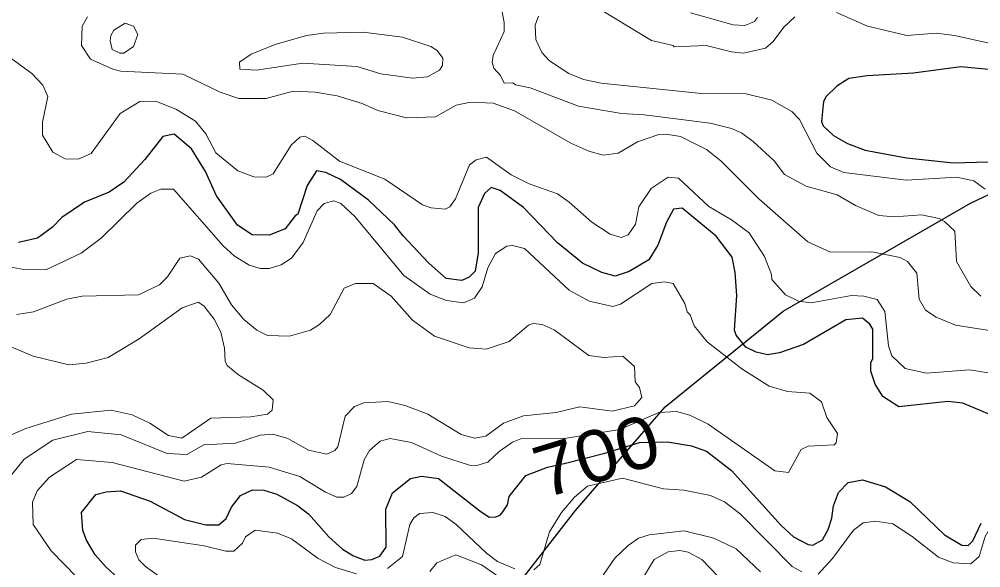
# Model space of a CAD drawing. Extents: x 673.3 to 698.5, y 6984.3 to 7012.3.
# Drawn here: x 674.164 to 675.656, y 6993.355 to 6994.206 of the extents above; entities that cross this region are included whole.
import ezdxf
from ezdxf.enums import TextEntityAlignment as Align

# ---------------------------------------------------------------- set-up
doc = ezdxf.new("R2010")
doc.units = 0
doc.header["$LTSCALE"] = 0.032
for name, color, linetype, lineweight in [('1', 7, 'Continuous', 25), ('2', 7, 'Continuous', 13), ('26', 7, 'Continuous', 25)]:
    doc.layers.add(name, color=color, linetype=linetype, lineweight=lineweight)
doc.layers.add('61', color=7, linetype='Continuous')

msp = doc.modelspace()

# ---------------------------------------------------------------- linework, layer by layer
at = {"layer": '1'}
for points in [[(675.7598, 6994.1193), (675.6253, 6994.1323), (675.552, 6994.1225), (675.4798, 6994.1185), (675.4514, 6994.1143), (675.4328, 6994.1022), (675.4162, 6994.0865), (675.4121, 6994.0786), (675.4092, 6994.0475), (675.4117, 6994.0409), (675.4277, 6994.026), (675.4494, 6994.0136), (675.477, 6994.0033), (675.5412, 6993.9914), (675.6139, 6993.9833), (675.6679, 6993.9849)], [(675.6679, 6993.594), (675.6285, 6993.6103), (675.6053, 6993.6128), (675.5289, 6993.6046), (675.5043, 6993.6208), (675.4923, 6993.6398), (675.4856, 6993.6599), (675.4856, 6993.673), (675.4888, 6993.6796), (675.4889, 6993.7253), (675.484, 6993.733), (675.4725, 6993.7421), (675.447, 6993.7396), (675.381, 6993.7014), (675.3441, 6993.6885), (675.3253, 6993.6854), (675.3077, 6993.6894), (675.2917, 6993.6975), (675.2765, 6993.7159), (675.2739, 6993.7235), (675.2778, 6993.7775), (675.2754, 6993.813), (675.2703, 6993.8369), (675.2457, 6993.8696), (675.1931, 6993.9131), (675.1797, 6993.9115), (675.1688, 6993.8913), (675.1551, 6993.8557), (675.1411, 6993.8328), (675.1106, 6993.8145), (675.089, 6993.8075), (675.0681, 6993.8129), (675.0384, 6993.8278), (674.9996, 6993.8593), (674.9467, 6993.9138), (674.9104, 6993.9405), (674.8968, 6993.9449), (674.8862, 6993.936), (674.8764, 6993.914), (674.8763, 6993.8437), (674.8717, 6993.8152), (674.8624, 6993.8061), (674.8512, 6993.8009), (674.8267, 6993.8039), (674.7998, 6993.8277), (674.7594, 6993.8706), (674.7466, 6993.8874), (674.7064, 6993.9252), (674.6627, 6993.9574), (674.6402, 6993.9686), (674.6256, 6993.9709), (674.611, 6993.9483), (674.5966, 6993.9035), (674.5925, 6993.9013), (674.5771, 6993.8811), (674.5522, 6993.871), (674.526, 6993.8715), (674.5031, 6993.8867), (674.4707, 6993.9322), (674.4536, 6993.9697), (674.4317, 6994.0052), (674.4048, 6994.0279), (674.3872, 6994.0241), (674.3591, 6993.9885), (674.3267, 6993.9534), (674.3041, 6993.9378), (674.2656, 6993.9222), (674.2305, 6993.8985), (674.2161, 6993.8835), (674.1925, 6993.8662), (674.1633, 6993.8596)], [(674.3319, 6993.3258), (674.2984, 6993.3567), (674.2823, 6993.3751), (674.2687, 6993.3978), (674.2631, 6993.4127), (674.2608, 6993.4406), (674.2831, 6993.4687), (674.2995, 6993.4728), (674.3217, 6993.4742), (674.3676, 6993.4583), (674.4206, 6993.4295), (674.4538, 6993.4217), (674.4743, 6993.4216), (674.4854, 6993.4312), (674.4935, 6993.4487), (674.5075, 6993.4668), (674.5262, 6993.4759), (674.5439, 6993.4751), (674.5643, 6993.4692), (674.596, 6993.4516), (674.6136, 6993.4382), (674.6448, 6993.4029), (674.6662, 6993.3839), (674.6828, 6993.3732), (674.7006, 6993.3668), (674.7113, 6993.3676), (674.7241, 6993.3726), (674.7335, 6993.3867), (674.7334, 6993.4459), (674.7437, 6993.471), (674.7713, 6993.4932), (674.7884, 6993.497), (674.8147, 6993.4936), (674.8789, 6993.443), (674.8936, 6993.4336), (674.904, 6993.4337), (674.9106, 6993.4367), (674.9146, 6993.4418), (674.9219, 6993.4524), (674.9243, 6993.4654), (674.9505, 6993.4978), (674.9842, 6993.511), (675.0101, 6993.5165), (675.073, 6993.5326), (675.1268, 6993.5494), (675.17, 6993.5504), (675.2074, 6993.5442), (675.2307, 6993.5358), (675.2696, 6993.5056), (675.3464, 6993.4204), (675.3656, 6993.4028), (675.3886, 6993.391), (675.3959, 6993.3901), (675.4108, 6993.398), (675.4195, 6993.4141)], [(675.4195, 6993.4141), (675.4252, 6993.4319), (675.4277, 6993.4512), (675.4356, 6993.4716), (675.4506, 6993.4872), (675.4728, 6993.4913), (675.5086, 6993.4806), (675.5464, 6993.4575), (675.5998, 6993.4057), (675.6266, 6993.3899), (675.6367, 6993.3896), (675.6439, 6993.3968), (675.6567, 6993.4241)]]:
    msp.add_lwpolyline(points, dxfattribs=at)
at = {"layer": '2'}
for points in [[(674.9114, 6994.2283), (674.917, 6994.201), (674.917, 6994.1871), (674.8996, 6994.1499), (674.8983, 6994.1392), (674.9005, 6994.1304), (674.9112, 6994.1187), (674.9166, 6994.1072), (674.93, 6994.1077), (674.9342, 6994.1044), (674.9572, 6994.0999), (675.0321, 6994.0714), (675.0989, 6994.0599), (675.134, 6994.0581), (675.2366, 6994.0451), (675.2695, 6994.0368), (675.285, 6994.0298)], [(675.3677, 6994.21), (675.3507, 6994.1939), (675.3342, 6994.1717), (675.3223, 6994.1616), (675.288, 6994.1536), (675.2695, 6994.1558), (675.2301, 6994.1656), (675.1804, 6994.1633), (675.179, 6994.1656), (675.1451, 6994.1734), (675.0694, 6994.2193)], [(675.3096, 6994.209), (675.3052, 6994.2029), (675.2902, 6994.1967), (675.2719, 6994.1975), (675.206, 6994.216)], [(675.7444, 6994.1528), (675.6152, 6994.1812), (675.5871, 6994.1844), (675.5415, 6994.1812), (675.4807, 6994.1953), (675.4324, 6994.2165)], [(674.2704, 6994.2102), (674.262, 6994.1953), (674.2608, 6994.1656), (674.2748, 6994.1445), (674.3095, 6994.1287), (674.322, 6994.1258), (674.4184, 6994.1209), (674.476, 6994.093), (674.505, 6994.0834), (674.5476, 6994.0835), (674.5894, 6994.0948), (674.6236, 6994.0933), (674.6578, 6994.0875), (674.6962, 6994.0756), (674.7207, 6994.0644), (674.7651, 6994.0531), (674.8104, 6994.055), (674.8423, 6994.0728), (674.8643, 6994.0776), (674.8996, 6994.076), (674.9328, 6994.0642), (675.02, 6994.0141), (675.048, 6994.0015), (675.0702, 6993.9955), (675.0936, 6993.9982), (675.1238, 6994.0161), (675.1565, 6994.0272), (675.1679, 6994.028), (675.1904, 6994.024), (675.2308, 6994.004), (675.2529, 6993.9863), (675.3118, 6993.9274), (675.3877, 6993.8607), (675.4232, 6993.8446), (675.487, 6993.845), (675.5311, 6993.8366), (675.5427, 6993.83), (675.5569, 6993.812), (675.5606, 6993.772), (675.5707, 6993.7549), (675.587, 6993.7438), (675.6169, 6993.7315), (675.7057, 6993.7176)], [(674.97, 6994.2112), (674.9651, 6994.1971), (674.9659, 6994.1749), (674.9753, 6994.1545), (674.9873, 6994.1419), (675.017, 6994.1222), (675.0399, 6994.1129), (675.0672, 6994.107), (675.2227, 6994.0911), (675.292, 6994.0907), (675.3319, 6994.0805), (675.3633, 6994.063), (675.3749, 6994.0506), (675.4018, 6993.9986), (675.4233, 6993.9771), (675.4438, 6993.9684), (675.5403, 6993.9564), (675.6191, 6993.9612), (675.6452, 6993.9557), (675.663, 6993.9425)], [(675.6676, 6993.6576), (675.6389, 6993.6623), (675.5719, 6993.6567), (675.5391, 6993.6644), (675.5181, 6993.6836), (675.5132, 6993.6993), (675.5075, 6993.7528), (675.4957, 6993.7715), (675.475, 6993.7765), (675.4556, 6993.7772), (675.3932, 6993.7659), (675.3732, 6993.7687), (675.3535, 6993.7784), (675.332, 6993.8021), (675.3316, 6993.8098), (675.3208, 6993.838), (675.2967, 6993.8747), (675.2694, 6993.8947), (675.2342, 6993.9155), (675.1871, 6993.9596), (675.1712, 6993.9611), (675.1447, 6993.9436), (675.1257, 6993.915), (675.1206, 6993.8883), (675.1091, 6993.8717), (675.0984, 6993.8677), (675.0814, 6993.8726), (675.0526, 6993.8911), (675.0178, 6993.9225), (674.9993, 6993.9352), (674.9556, 6993.9509), (674.9274, 6993.965), (674.8891, 6993.9922), (674.8733, 6993.9882), (674.8629, 6993.9802), (674.8415, 6993.9277), (674.8324, 6993.9151), (674.8253, 6993.9116), (674.8035, 6993.9137), (674.7903, 6993.918), (674.7314, 6993.958), (674.6611, 6993.9862), (674.6201, 6994.018), (674.6074, 6994.0247), (674.5995, 6994.0231), (674.5864, 6994.0109), (674.5584, 6993.9661), (674.5473, 6993.9613), (674.5284, 6993.9615), (674.5036, 6993.971), (674.4693, 6993.9988), (674.4541, 6994.0286), (674.438, 6994.0478), (674.4084, 6994.0662), (674.3763, 6994.0793), (674.3514, 6994.0785), (674.3212, 6994.06), (674.2761, 6993.998), (674.2558, 6993.989), (674.2357, 6993.9898), (674.2167, 6993.9998), (674.2005, 6994.0264), (674.2005, 6994.0467), (674.2086, 6994.0863), (674.2011, 6994.1037), (674.1839, 6994.1219), (674.1494, 6994.1475)], [(675.285, 6994.0298), (675.3032, 6994.0167), (675.3358, 6993.9863), (675.3519, 6993.9654), (675.3851, 6993.9472), (675.4332, 6993.9335), (675.4617, 6993.917), (675.4983, 6993.9015), (675.5223, 6993.8994), (675.5643, 6993.9026), (675.5917, 6993.8968), (675.5999, 6993.8925), (675.6158, 6993.8771), (675.6183, 6993.8302), (675.6408, 6993.7912), (675.6563, 6993.7766)], [(674.1486, 6993.822), (674.1717, 6993.818), (674.2058, 6993.8172), (674.2607, 6993.8431), (674.2917, 6993.8665), (674.3467, 6993.9209), (674.3685, 6993.9365), (674.3842, 6993.9425), (674.4038, 6993.9425), (674.481, 6993.8543), (674.4978, 6993.8388), (674.521, 6993.8243), (674.5386, 6993.8196), (674.5522, 6993.8196), (674.5709, 6993.8248), (674.5869, 6993.8355), (674.6048, 6993.8597), (674.6264, 6993.9091), (674.6373, 6993.9205), (674.6525, 6993.9246), (674.6631, 6993.9203), (674.6849, 6993.9002), (674.7611, 6993.8086), (674.8017, 6993.7796), (674.8272, 6993.7699), (674.8536, 6993.7659), (674.8706, 6993.7733), (674.8827, 6993.7909), (674.8913, 6993.8202), (674.9031, 6993.8429), (674.9211, 6993.8541), (674.9295, 6993.8553), (674.9481, 6993.8505), (675.0176, 6993.7855), (675.0484, 6993.7685), (675.0856, 6993.7602), (675.0973, 6993.7639), (675.146, 6993.7959), (675.1654, 6993.7985), (675.179, 6993.7959), (675.1972, 6993.765), (675.2006, 6993.752), (675.2052, 6993.7474), (675.2115, 6993.7306), (675.2317, 6993.7053), (675.2854, 6993.6636), (675.3279, 6993.6369), (675.3565, 6993.6282), (675.391, 6993.6257), (675.4089, 6993.6126), (675.4173, 6993.5881), (675.4341, 6993.5631), (675.4317, 6993.5488)], [(674.8086, 6993.7143), (674.7743, 6993.7392), (674.7414, 6993.7762), (674.7136, 6993.796), (674.6861, 6993.796), (674.6686, 6993.7889), (674.6466, 6993.748), (674.6302, 6993.7323), (674.6165, 6993.7238), (674.5838, 6993.7144), (674.5497, 6993.7152), (674.533, 6993.7234), (674.5129, 6993.74), (674.4936, 6993.763), (674.474, 6993.7968), (674.4425, 6993.834), (674.4299, 6993.8391), (674.4138, 6993.8355), (674.3942, 6993.8065), (674.3822, 6993.7942), (674.3492, 6993.7783), (674.2623, 6993.7764), (674.2382, 6993.7716), (674.1865, 6993.7521), (674.1607, 6993.7479)], [(674.0891, 6993.7244), (674.1861, 6993.6834), (674.2416, 6993.6697), (674.2684, 6993.6726), (674.3022, 6993.6812), (674.3503, 6993.7101), (674.4173, 6993.7581), (674.442, 6993.7673), (674.4506, 6993.7615), (674.4667, 6993.7405), (674.4772, 6993.7205), (674.483, 6993.6958), (674.4839, 6993.6757), (674.4872, 6993.669), (674.5046, 6993.6543), (674.5428, 6993.6304), (674.5584, 6993.6153), (674.557, 6993.5996), (674.5494, 6993.5932), (674.5239, 6993.5891), (674.4617, 6993.5868), (674.4167, 6993.5561), (674.3962, 6993.5604), (674.3672, 6993.5791), (674.3395, 6993.5921), (674.3069, 6993.5996), (674.2454, 6993.5934), (674.1744, 6993.5711), (674.1256, 6993.55)], [(674.1508, 6993.497), (674.1722, 6993.5233), (674.2165, 6993.5531), (674.2708, 6993.5663), (674.3228, 6993.5613), (674.3939, 6993.5321), (674.4245, 6993.5309), (674.4508, 6993.5459), (674.4998, 6993.5484), (674.538, 6993.5607), (674.5577, 6993.5622), (674.5813, 6993.5557), (674.6132, 6993.5376), (674.6418, 6993.5313), (674.6541, 6993.5371), (674.6587, 6993.5424), (674.67, 6993.5904), (674.6844, 6993.6054), (674.6988, 6993.611), (674.7363, 6993.6127), (674.7634, 6993.6067), (674.7982, 6993.5931), (674.8503, 6993.5615), (674.8709, 6993.5558), (674.8882, 6993.5589), (674.9157, 6993.5795), (674.9467, 6993.5908), (674.9974, 6993.5957), (675.034, 6993.6045), (675.0845, 6993.5981), (675.119, 6993.6062), (675.1305, 6993.619), (675.1266, 6993.6349), (675.1199, 6993.6432), (675.1188, 6993.6674), (675.1008, 6993.6835), (675.0707, 6993.6811), (675.0479, 6993.6843), (674.9944, 6993.7242), (674.9757, 6993.7324), (674.9616, 6993.7339), (674.9545, 6993.7314), (674.9246, 6993.7061), (674.8888, 6993.6942), (674.8623, 6993.696), (674.8086, 6993.7143)], [(675.4317, 6993.5488), (675.4287, 6993.5454), (675.3885, 6993.5435), (675.3773, 6993.5385), (675.3581, 6993.5028), (675.3367, 6993.5053), (675.2331, 6993.5776), (675.2049, 6993.5919), (675.1839, 6993.5973), (675.1566, 6993.596), (675.0964, 6993.5694), (675.0134, 6993.5559), (674.9424, 6993.5551), (674.9299, 6993.5499), (674.909, 6993.5353), (674.8916, 6993.5189), (674.8741, 6993.5134), (674.863, 6993.5142), (674.8194, 6993.5281), (674.7732, 6993.5493), (674.7399, 6993.5556), (674.7243, 6993.5516), (674.7077, 6993.537), (674.6994, 6993.5225), (674.6881, 6993.4808), (674.6799, 6993.47), (674.6681, 6993.4645), (674.6572, 6993.4646), (674.6395, 6993.4721), (674.5997, 6993.4965), (674.5522, 6993.5109), (674.4872, 6993.5166), (674.4778, 6993.5147), (674.447, 6993.4955), (674.4201, 6993.489), (674.3085, 6993.5181), (674.2531, 6993.5229), (674.2112, 6993.4956), (674.192, 6993.4742), (674.185, 6993.4566), (674.1859, 6993.4222), (674.2138, 6993.381), (674.2538, 6993.3403)], [(675.3787, 6993.3484), (675.3638, 6993.3569), (675.2831, 6993.4388), (675.2586, 6993.457), (675.237, 6993.4671), (675.1954, 6993.4751), (675.1641, 6993.4776), (675.1001, 6993.4938), (675.0459, 6993.4815), (675.0259, 6993.4642), (675.0055, 6993.4406), (674.987, 6993.4105), (674.9721, 6993.3599), (674.963, 6993.3516)], [(675.8485, 6993.3343), (675.8136, 6993.3668), (675.7924, 6993.3996), (675.7785, 6993.442), (675.7585, 6993.467), (675.7418, 6993.4693), (675.7232, 6993.4678), (675.7, 6993.4516), (675.6727, 6993.4203), (675.6628, 6993.4036), (675.6539, 6993.3723), (675.6406, 6993.3611), (675.6136, 6993.3627), (675.5907, 6993.3712), (675.5496, 6993.4036), (675.5196, 6993.4228), (675.4931, 6993.427), (675.474, 6993.4247), (675.4589, 6993.4133), (675.4262, 6993.3694), (675.4038, 6993.3448)], [(674.9334, 6993.3534), (674.9063, 6993.3648), (674.8892, 6993.3775), (674.842, 6993.4223), (674.825, 6993.4343), (674.8063, 6993.4408), (674.7852, 6993.4392), (674.7768, 6993.4326), (674.7705, 6993.4218), (674.759, 6993.3725), (674.7358, 6993.3539)], [(674.6878, 6993.3456), (674.6551, 6993.3552), (674.6282, 6993.3694), (674.587, 6993.3995), (674.5653, 6993.4083), (674.5306, 6993.4133), (674.5154, 6993.403), (674.5108, 6993.3931), (674.4976, 6993.3805), (674.4849, 6993.3806), (674.4513, 6993.3887), (674.372, 6993.4009), (674.3538, 6993.3986), (674.3446, 6993.3901), (674.3449, 6993.3798), (674.3498, 6993.3674), (674.3604, 6993.3568), (674.4079, 6993.3229)], [(675.3143, 6993.3483), (675.2768, 6993.384), (675.2419, 6993.4007), (675.1959, 6993.4123), (675.1418, 6993.4058), (675.1254, 6993.4007), (675.1093, 6993.3896), (675.0885, 6993.3695), (675.0508, 6993.3149)], [(675.2861, 6993.3025), (675.2232, 6993.3676), (675.2021, 6993.3789), (675.1891, 6993.3815), (675.1712, 6993.3798), (675.1494, 6993.3677), (675.1321, 6993.3387)], [(674.9786, 6993.2921), (674.8815, 6993.3593), (674.8419, 6993.3748), (674.8121, 6993.3626), (674.8015, 6993.3488)]]:
    msp.add_lwpolyline(points, dxfattribs=at)
for points in [[(674.3484, 6994.1825), (674.3415, 6994.1955), (674.329, 6994.2004), (674.3111, 6994.1891), (674.3063, 6994.1811), (674.3055, 6994.1728), (674.3088, 6994.1594), (674.3204, 6994.1536), (674.3266, 6994.1536), (674.3418, 6994.1638)], [(674.7252, 6994.1217), (674.7748, 6994.1147), (674.7979, 6994.1168), (674.8165, 6994.127), (674.8211, 6994.1345), (674.8218, 6994.1459), (674.8126, 6994.1576), (674.8029, 6994.164), (674.7591, 6994.1787), (674.6978, 6994.186), (674.6363, 6994.1844), (674.61, 6994.1809), (674.5614, 6994.1669), (674.5245, 6994.1518), (674.5061, 6994.1394), (674.5067, 6994.1289), (674.5323, 6994.1274), (674.6042, 6994.1379), (674.688, 6994.133)]]:
    msp.add_lwpolyline(points, close=True, dxfattribs=at)
at = {"layer": '26'}
msp.add_lwpolyline([(674.8631, 6993.232), (675.0274, 6993.4436), (675.1664, 6993.6047), (675.3496, 6993.7532), (675.6402, 6993.9206), (676.0729, 6994.1259), (676.613, 6994.2965), (676.7393, 6994.3312), (676.9068, 6994.3596), (677.0141, 6994.3723), (677.1658, 6994.3975), (677.3742, 6994.467), (677.5164, 6994.5397)], dxfattribs=at)

# ---------------------------------------------------------------- texts
at = {"layer": '61', "width": 1.1}
msp.add_text('700', height=0.08, rotation=16.928, dxfattribs=at).set_placement((675.0717, 6993.4905), align=Align.CENTER)

doc.saveas('drawing.dxf')
